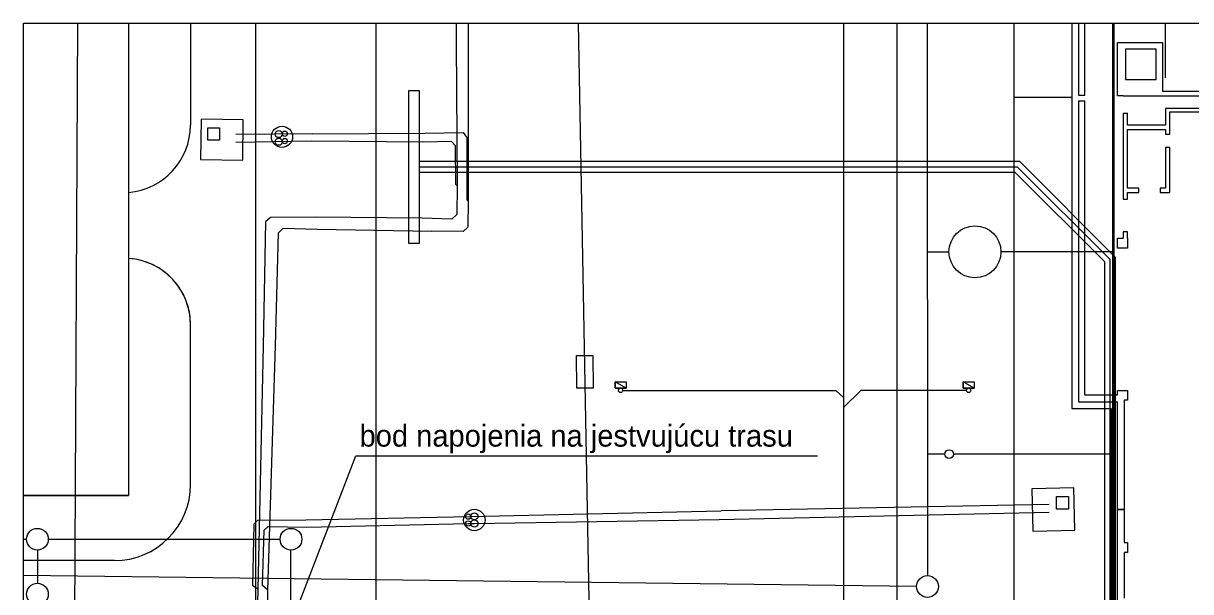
# Model space of a CAD drawing. Extents: x -263964 to -263859, y -1242287 to -1242158.
# Drawn here: x -263964.3 to -263910.6, y -1242183.9 to -1242157.8 of the extents above; entities that cross this region are included whole.
import ezdxf

# ---------------------------------------------------------------- set-up
doc = ezdxf.new("R2010")
doc.units = 0
for name, color, linetype in [('KFA_2D_JESTVUJUCE_IS_DSP', 7, 'Continuous'), ('KFA_2D_SITUACIA_DSP', 7, 'Continuous'), ('KFA_BETONY_HL_B_1PP', 7, 'Continuous'), ('KFA_JESTVUJUCI_HORUCOVOD', 7, 'Continuous'), ('POPIS', 7, 'Continuous'), ('RAM_NA_TLAC_A3_1-250', 7, 'Continuous')]:
    doc.layers.add(name, color=color, linetype=linetype)

msp = doc.modelspace()

# ---------------------------------------------------------------- linework, layer by layer
at = {"layer": 'KFA_2D_JESTVUJUCE_IS_DSP'}
for p, q in [((-263961.81, -1242157.773), (-263961.999, -1242192.922)), ((-263937.993, -1242200.068), (-263938.781, -1242157.773)), ((-263922.752, -1242157.773), (-263922.734, -1242183.174)), ((-263918.763, -1242157.773), (-263918.757, -1242196.225)), ((-263938.869, -1242173.048), (-263938.119, -1242173.046)), ((-263938.863, -1242174.548), (-263938.869, -1242173.048)), ((-263938.119, -1242173.046), (-263938.113, -1242174.546)), ((-263938.113, -1242174.546), (-263938.863, -1242174.548)), ((-263938.863, -1242174.548), (-263938.863, -1242174.548)), ((-263923.234, -1242183.668), (-263964.307, -1242183.176))]:
    msp.add_line(p, q, dxfattribs=at)
for centre in [(-263922.734, -1242183.674), (-263963.661, -1242184.028)]:
    msp.add_circle(centre, 0.5, dxfattribs=at)
at = {"layer": 'KFA_2D_SITUACIA_DSP'}
for p, q in [((-263959.468, -1242157.773), (-263959.468, -1242179.482)), ((-263956.618, -1242157.773), (-263956.618, -1242162.449)), ((-263953.617, -1242232.023), (-263953.617, -1242157.773)), ((-263948.093, -1242157.773), (-263948.093, -1242232.023)), ((-263926.593, -1242157.773), (-263926.593, -1242204.252)), ((-263924.143, -1242157.773), (-263924.143, -1242185.14)), ((-263916.093, -1242157.773), (-263916.093, -1242175.482)), ((-263914.218, -1242196.332), (-263914.218, -1242157.773)), ((-263914.143, -1242196.333), (-263914.143, -1242157.773)), ((-263946.093, -1242160.882), (-263946.593, -1242160.882)), ((-263946.593, -1242160.882), (-263946.593, -1242167.882)), ((-263946.093, -1242167.882), (-263946.093, -1242160.882)), ((-263916.093, -1242161.182), (-263918.763, -1242161.182)), ((-263918.489, -1242164.132), (-263946.093, -1242164.132)), ((-263918.593, -1242164.382), (-263946.093, -1242164.382)), ((-263918.593, -1242164.382), (-263914.35, -1242168.625)), ((-263918.489, -1242164.132), (-263914.1, -1242168.521)), ((-263918.696, -1242164.632), (-263946.093, -1242164.632)), ((-263918.696, -1242164.632), (-263914.6, -1242168.728)), ((-263959.468, -1242165.549), (-263959.468, -1242165.549)), ((-263946.593, -1242167.882), (-263946.093, -1242167.882)), ((-263922.745, -1242168.282), (-263921.745, -1242168.282)), ((-263914.143, -1242168.282), (-263919.355, -1242168.282)), ((-263959.273, -1242168.601), (-263959.468, -1242168.582)), ((-263959.467, -1242168.582), (-263959.467, -1242168.582)), ((-263959.056, -1242168.638), (-263959.273, -1242168.601)), ((-263958.842, -1242168.69), (-263959.056, -1242168.638)), ((-263958.45, -1242168.829), (-263958.842, -1242168.69)), ((-263914.6, -1242168.728), (-263914.6, -1242199.693)), ((-263914.35, -1242168.625), (-263914.35, -1242199.59)), ((-263914.1, -1242168.521), (-263914.1, -1242199.486)), ((-263958.077, -1242169.024), (-263958.45, -1242168.829)), ((-263957.705, -1242169.291), (-263958.077, -1242169.024)), ((-263957.435, -1242169.549), (-263957.705, -1242169.291)), ((-263957.158, -1242169.893), (-263957.435, -1242169.549)), ((-263956.87, -1242170.411), (-263957.158, -1242169.893)), ((-263956.707, -1242170.894), (-263956.87, -1242170.411)), ((-263956.64, -1242171.257), (-263956.707, -1242170.894)), ((-263956.618, -1242171.626), (-263956.64, -1242171.257)), ((-263956.618, -1242178.982), (-263956.618, -1242171.626)), ((-263956.618, -1242178.982), (-263956.618, -1242171.645)), ((-263937.093, -1242174.553), (-263937.093, -1242174.263)), ((-263937.093, -1242174.263), (-263936.593, -1242174.263)), ((-263936.593, -1242174.553), (-263937.093, -1242174.263)), ((-263936.593, -1242174.553), (-263937.093, -1242174.263)), ((-263937.093, -1242174.263), (-263937.093, -1242174.553)), ((-263936.593, -1242174.553), (-263937.093, -1242174.553)), ((-263937.093, -1242174.553), (-263936.593, -1242174.553)), ((-263936.743, -1242174.653), (-263926.953, -1242174.653)), ((-263936.593, -1242174.263), (-263936.593, -1242174.553)), ((-263926.953, -1242174.653), (-263926.593, -1242174.978)), ((-263925.798, -1242174.653), (-263926.593, -1242175.448)), ((-263920.944, -1242174.653), (-263925.798, -1242174.653)), ((-263921.093, -1242174.553), (-263921.093, -1242174.263)), ((-263921.093, -1242174.263), (-263920.593, -1242174.263)), ((-263920.593, -1242174.553), (-263921.093, -1242174.263)), ((-263920.593, -1242174.553), (-263921.093, -1242174.263)), ((-263921.093, -1242174.263), (-263921.093, -1242174.553)), ((-263920.593, -1242174.553), (-263921.093, -1242174.553)), ((-263921.093, -1242174.553), (-263920.593, -1242174.553)), ((-263920.593, -1242174.263), (-263920.593, -1242174.553)), ((-263916.093, -1242175.482), (-263914.293, -1242175.482)), ((-263914.293, -1242175.482), (-263914.293, -1242210.482)), ((-263921.938, -1242177.582), (-263922.738, -1242177.582)), ((-263915.293, -1242177.582), (-263921.538, -1242177.582)), ((-263914.143, -1242177.582), (-263915.293, -1242177.582)), ((-263956.618, -1242178.982), (-263956.618, -1242178.982)), ((-263959.468, -1242179.482), (-263964.307, -1242179.482)), ((-263964.307, -1242179.482), (-263959.468, -1242179.482)), ((-263959.468, -1242179.482), (-263964.307, -1242179.482)), ((-263964.307, -1242181.5), (-263964.161, -1242181.5)), ((-263963.161, -1242181.5), (-263952.5, -1242181.5)), ((-263963.661, -1242182), (-263963.661, -1242183.528)), ((-263952, -1242222.527), (-263952, -1242182)), ((-263960.118, -1242182.482), (-263964.307, -1242182.482))]:
    msp.add_line(p, q, dxfattribs=at)
for centre, radius in [((-263920.55, -1242168.282), 1.195), ((-263936.843, -1242174.653), 0.1), ((-263920.844, -1242174.653), 0.1), ((-263921.738, -1242177.582), 0.2), ((-263963.661, -1242181.5), 0.5), ((-263952, -1242181.5), 0.5)]:
    msp.add_circle(centre, radius, dxfattribs=at)
for centre, radius, start, end in [((-263959.738, -1242162.441), 3.12, 274.9637, 359.8482), ((-263959.668, -1242171.626), 3.05, 359.6441, 86.2155), ((-263960.118, -1242178.982), 3.5, 270, 0)]:
    msp.add_arc(centre, radius, start, end, dxfattribs=at)
at = {"layer": 'KFA_BETONY_HL_B_1PP'}
for p, q in [((-263915.793, -1242157.773), (-263915.793, -1242161.082)), ((-263915.493, -1242161.082), (-263915.493, -1242157.773)), ((-263913.993, -1242160.657), (-263913.993, -1242158.657)), ((-263913.993, -1242158.657), (-263913.63, -1242158.657)), ((-263913.63, -1242158.657), (-263912.22, -1242158.657)), ((-263912.22, -1242158.957), (-263913.63, -1242158.957)), ((-263913.63, -1242158.957), (-263913.63, -1242160.357)), ((-263912.22, -1242158.657), (-263911.92, -1242158.657)), ((-263912.22, -1242160.357), (-263912.22, -1242158.957)), ((-263911.92, -1242158.657), (-263911.92, -1242160.357)), ((-263913.993, -1242161.107), (-263913.993, -1242160.657)), ((-263913.63, -1242160.357), (-263912.22, -1242160.357)), ((-263911.92, -1242160.357), (-263911.92, -1242160.907)), ((-263915.793, -1242161.082), (-263915.493, -1242161.082)), ((-263913.743, -1242161.107), (-263913.993, -1242161.107)), ((-263913.743, -1242161.107), (-263913.543, -1242161.107)), ((-263913.543, -1242161.107), (-263913.16, -1242161.107)), ((-263913.16, -1242161.107), (-263912.71, -1242161.107)), ((-263912.71, -1242161.107), (-263911.793, -1242161.107)), ((-263911.793, -1242160.907), (-263911.92, -1242160.907)), ((-263910.143, -1242160.907), (-263911.793, -1242160.907)), ((-263911.793, -1242161.107), (-263908.893, -1242161.107)), ((-263915.793, -1242161.332), (-263915.793, -1242168.182)), ((-263915.793, -1242161.332), (-263915.493, -1242161.332)), ((-263915.493, -1242168.182), (-263915.493, -1242161.332)), ((-263911.793, -1242161.687), (-263911.793, -1242161.887)), ((-263908.893, -1242161.687), (-263911.793, -1242161.687)), ((-263911.593, -1242161.837), (-263908.893, -1242161.837)), ((-263911.593, -1242161.887), (-263911.593, -1242161.837)), ((-263911.593, -1242161.887), (-263911.593, -1242161.837)), ((-263913.743, -1242161.907), (-263913.743, -1242165.857)), ((-263913.743, -1242161.907), (-263913.543, -1242161.907)), ((-263913.543, -1242162.457), (-263913.543, -1242161.907)), ((-263911.793, -1242161.887), (-263911.793, -1242162.457)), ((-263911.593, -1242162.457), (-263911.593, -1242161.887)), ((-263911.593, -1242162.457), (-263911.593, -1242161.887)), ((-263911.793, -1242162.457), (-263913.543, -1242162.457)), ((-263913.543, -1242162.657), (-263911.793, -1242162.657)), ((-263913.543, -1242165.357), (-263913.543, -1242162.657)), ((-263911.793, -1242162.657), (-263911.793, -1242162.863)), ((-263911.793, -1242162.863), (-263911.593, -1242162.863)), ((-263911.593, -1242162.863), (-263911.593, -1242162.457)), ((-263911.593, -1242162.863), (-263911.593, -1242162.457)), ((-263911.793, -1242163.463), (-263911.793, -1242165.357)), ((-263911.793, -1242163.463), (-263911.593, -1242163.463)), ((-263911.593, -1242165.357), (-263911.593, -1242163.463)), ((-263911.593, -1242165.357), (-263911.593, -1242163.463)), ((-263913.01, -1242165.357), (-263913.543, -1242165.357)), ((-263913.543, -1242165.557), (-263913.01, -1242165.557)), ((-263913.543, -1242165.857), (-263913.543, -1242165.557)), ((-263913.01, -1242165.557), (-263913.01, -1242165.357)), ((-263911.793, -1242165.357), (-263912.03, -1242165.357)), ((-263912.03, -1242165.357), (-263912.03, -1242165.557)), ((-263912.03, -1242165.557), (-263911.593, -1242165.557)), ((-263911.593, -1242165.557), (-263911.593, -1242165.357)), ((-263913.743, -1242165.857), (-263913.543, -1242165.857)), ((-263913.993, -1242168.107), (-263913.993, -1242167.657)), ((-263913.993, -1242167.657), (-263913.743, -1242167.657)), ((-263913.743, -1242167.357), (-263913.743, -1242167.657)), ((-263913.543, -1242167.357), (-263913.743, -1242167.357)), ((-263913.543, -1242167.657), (-263913.543, -1242167.357)), ((-263913.543, -1242167.657), (-263913.543, -1242168.107)), ((-263915.793, -1242168.182), (-263915.793, -1242168.382)), ((-263915.493, -1242168.382), (-263915.493, -1242168.182)), ((-263913.543, -1242168.107), (-263913.993, -1242168.107)), ((-263915.793, -1242168.382), (-263915.793, -1242175.182)), ((-263915.493, -1242174.882), (-263915.493, -1242168.382)), ((-263913.993, -1242174.657), (-263913.543, -1242174.657)), ((-263913.993, -1242174.882), (-263913.993, -1242174.657)), ((-263913.543, -1242174.657), (-263913.543, -1242175.107)), ((-263915.793, -1242175.182), (-263915.493, -1242175.182)), ((-263913.993, -1242174.882), (-263915.493, -1242174.882)), ((-263915.493, -1242175.182), (-263913.993, -1242175.182)), ((-263913.993, -1242180.112), (-263913.993, -1242175.182)), ((-263913.543, -1242175.107), (-263913.693, -1242175.107)), ((-263913.693, -1242175.107), (-263913.693, -1242180.112)), ((-263913.543, -1242175.107), (-263913.693, -1242175.107)), ((-263913.993, -1242180.112), (-263913.693, -1242180.112)), ((-263913.993, -1242181.657), (-263913.993, -1242180.132)), ((-263913.993, -1242180.132), (-263913.693, -1242180.132)), ((-263913.693, -1242180.132), (-263913.693, -1242181.657)), ((-263913.993, -1242182.107), (-263913.993, -1242181.657)), ((-263913.693, -1242181.657), (-263913.543, -1242181.657)), ((-263913.543, -1242181.657), (-263913.543, -1242182.107)), ((-263913.993, -1242188.657), (-263913.993, -1242182.107)), ((-263913.543, -1242182.107), (-263913.693, -1242182.107)), ((-263913.693, -1242182.107), (-263913.693, -1242184.207))]:
    msp.add_line(p, q, dxfattribs=at)
at = {"layer": 'KFA_JESTVUJUCI_HORUCOVOD'}
for p, q in [((-263944.41, -1242157.773), (-263944.412, -1242158.664)), ((-263943.854, -1242157.773), (-263943.853, -1242158.652)), ((-263944.412, -1242158.664), (-263944.352, -1242165.249)), ((-263943.853, -1242158.652), (-263943.849, -1242165.958)), ((-263956.13, -1242162.18), (-263956.156, -1242164.04)), ((-263954.192, -1242162.207), (-263956.13, -1242162.18)), ((-263954.218, -1242164.067), (-263954.192, -1242162.207)), ((-263955.831, -1242163.152), (-263955.831, -1242162.573)), ((-263955.831, -1242162.573), (-263955.28, -1242162.573)), ((-263955.28, -1242162.573), (-263955.28, -1242163.152)), ((-263951.019, -1242162.854), (-263954.543, -1242162.888)), ((-263951.019, -1242162.854), (-263945.83, -1242162.832)), ((-263945.83, -1242162.832), (-263944.071, -1242162.801)), ((-263943.916, -1242163.012), (-263944.071, -1242162.801)), ((-263955.28, -1242163.152), (-263955.831, -1242163.152)), ((-263951.079, -1242163.196), (-263954.539, -1242163.255)), ((-263945.899, -1242163.231), (-263951.079, -1242163.196)), ((-263944.614, -1242163.211), (-263945.899, -1242163.231)), ((-263944.447, -1242163.393), (-263944.614, -1242163.211)), ((-263944.447, -1242163.393), (-263944.442, -1242165.164)), ((-263943.914, -1242163.012), (-263943.913, -1242165.895)), ((-263956.156, -1242164.04), (-263954.218, -1242164.067)), ((-263944.442, -1242165.164), (-263944.352, -1242165.249)), ((-263944.442, -1242165.164), (-263944.442, -1242165.164)), ((-263944.352, -1242165.249), (-263944.379, -1242166.564)), ((-263943.913, -1242165.895), (-263943.849, -1242165.958)), ((-263943.913, -1242165.895), (-263943.913, -1242165.895)), ((-263943.849, -1242165.958), (-263943.861, -1242167.143)), ((-263944.379, -1242166.564), (-263944.61, -1242166.777)), ((-263953.167, -1242166.907), (-263953.276, -1242172.621)), ((-263952.942, -1242166.698), (-263953.167, -1242166.907)), ((-263950.896, -1242166.694), (-263952.942, -1242166.698)), ((-263952.57, -1242167.416), (-263952.361, -1242167.2)), ((-263952.361, -1242167.2), (-263950.803, -1242167.244)), ((-263945.968, -1242166.741), (-263950.896, -1242166.694)), ((-263944.61, -1242166.777), (-263945.968, -1242166.741)), ((-263943.861, -1242167.143), (-263944.087, -1242167.347)), ((-263952.715, -1242172.612), (-263952.57, -1242167.416)), ((-263950.803, -1242167.244), (-263945.525, -1242167.325)), ((-263944.087, -1242167.347), (-263945.525, -1242167.325)), ((-263953.276, -1242172.621), (-263953.528, -1242183.799)), ((-263953.067, -1242183.845), (-263952.715, -1242172.612)), ((-263916.007, -1242179.139), (-263917.932, -1242179.184)), ((-263917.932, -1242179.184), (-263917.886, -1242181.133)), ((-263916.803, -1242180.116), (-263916.803, -1242179.537)), ((-263916.803, -1242179.537), (-263916.252, -1242179.537)), ((-263916.252, -1242179.537), (-263916.252, -1242180.116)), ((-263915.961, -1242181.088), (-263916.007, -1242179.139)), ((-263917.138, -1242179.908), (-263932.226, -1242180.187)), ((-263953.71, -1242180.8), (-263953.518, -1242180.617)), ((-263953.518, -1242180.617), (-263951.311, -1242180.614)), ((-263951.311, -1242180.614), (-263943.779, -1242180.456)), ((-263943.779, -1242180.456), (-263932.226, -1242180.187)), ((-263943.567, -1242180.776), (-263932.313, -1242180.597)), ((-263932.313, -1242180.597), (-263917.138, -1242180.263)), ((-263916.252, -1242180.116), (-263916.803, -1242180.116)), ((-263953.71, -1242180.8), (-263953.774, -1242183.629)), ((-263953.31, -1242183.629), (-263953.231, -1242181.09)), ((-263953.231, -1242181.09), (-263953.049, -1242180.917)), ((-263953.049, -1242180.917), (-263951.265, -1242180.941)), ((-263951.265, -1242180.941), (-263943.848, -1242180.778)), ((-263943.848, -1242180.778), (-263943.567, -1242180.776)), ((-263917.886, -1242181.133), (-263915.961, -1242181.088)), ((-263953.528, -1242183.799), (-263953.774, -1242183.629)), ((-263953.528, -1242183.799), (-263953.63, -1242189.514)), ((-263953.067, -1242183.845), (-263953.31, -1242183.629)), ((-263953.083, -1242189.456), (-263953.067, -1242183.845))]:
    msp.add_line(p, q, dxfattribs=at)
for centre, radius in [((-263952.413, -1242162.992), 0.487), ((-263952.568, -1242162.867), 0.164), ((-263952.284, -1242162.851), 0.122), ((-263952.568, -1242163.22), 0.164), ((-263952.284, -1242163.187), 0.122), ((-263943.568, -1242180.617), 0.496), ((-263943.848, -1242180.461), 0.122), ((-263943.567, -1242180.445), 0.164), ((-263943.567, -1242180.776), 0.164), ((-263943.848, -1242180.778), 0.122)]:
    msp.add_circle(centre, radius, dxfattribs=at)
at = {"layer": 'POPIS'}
for p, q in [((-263953.666, -1242189.744), (-263949.014, -1242177.664)), ((-263949.014, -1242177.664), (-263927.786, -1242177.664))]:
    msp.add_line(p, q, dxfattribs=at)
at = {"layer": 'RAM_NA_TLAC_A3_1-250'}
msp.add_line((-263911.807, -1242157.773), (-263911.807, -1242160.273), dxfattribs=at)
msp.add_lwpolyline([(-263964.307, -1242157.773), (-263859.307, -1242157.773), (-263859.307, -1242232.023), (-263964.307, -1242232.023)], close=True, dxfattribs=at)

# ---------------------------------------------------------------- texts
at = {"layer": 'POPIS'}
msp.add_text('bod napojenia na jestvujúcu trasu', height=1, dxfattribs=at).set_placement((-263948.847, -1242177.241))

doc.saveas('drawing.dxf')
